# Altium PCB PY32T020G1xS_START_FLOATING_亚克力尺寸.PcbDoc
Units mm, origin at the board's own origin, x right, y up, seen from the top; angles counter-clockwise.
Board outline 150 x 47.08 mm, 2 copper layers (Top Layer, Bottom Layer); 6 components, 46 nets, 6 pads, 0 vias.
Unrouted connection lines stored in the file: 5.
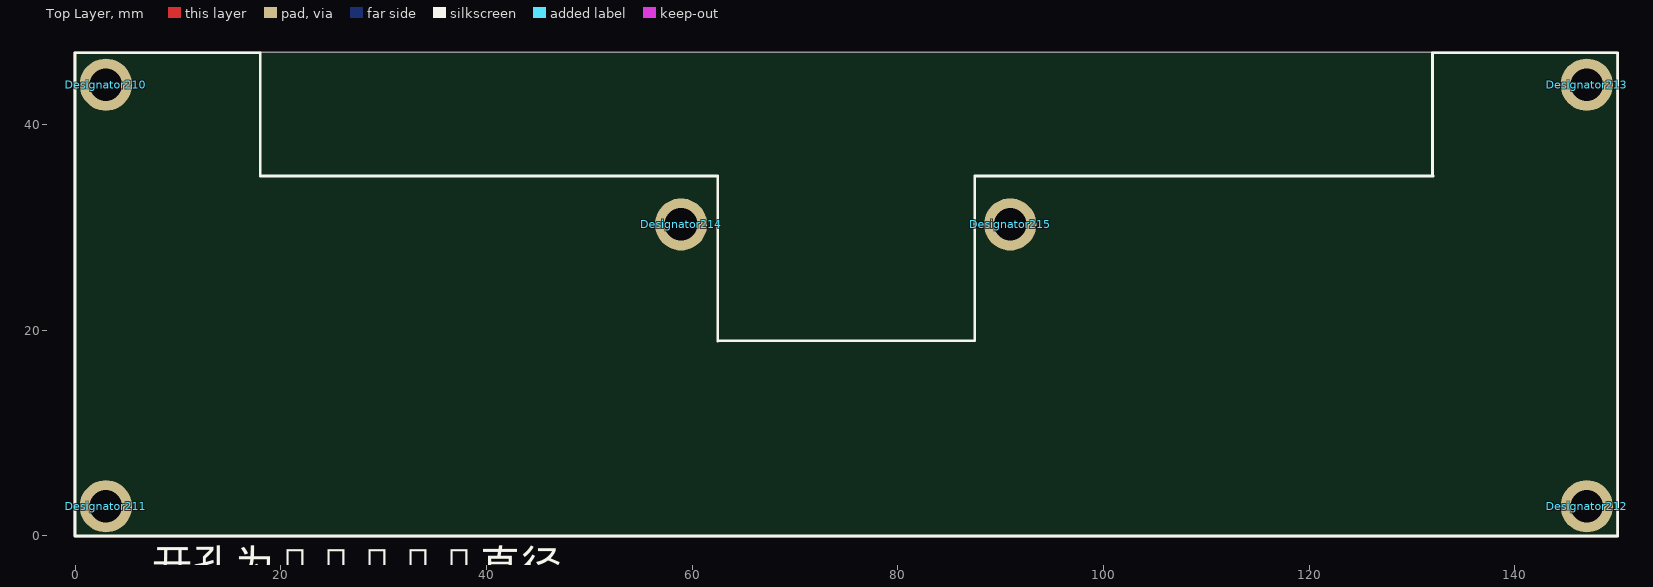
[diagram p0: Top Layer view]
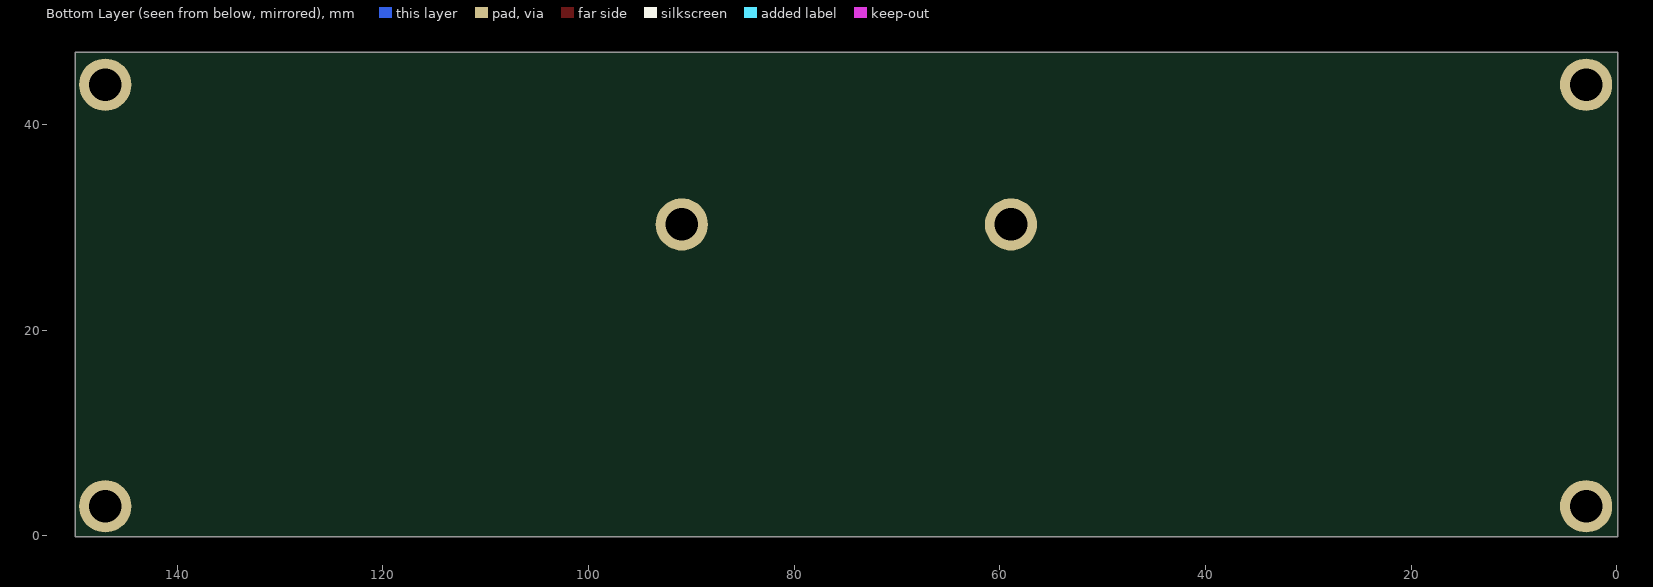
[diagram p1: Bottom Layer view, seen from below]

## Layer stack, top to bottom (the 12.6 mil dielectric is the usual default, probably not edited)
Top Solder: solder mask 0.0102, Solder Resist, Dk 3.5
Top Layer: signal copper 0.0356
Dielectric 1: dielectric 0.32, FR-4, Dk 4.8
Bottom Layer: signal copper 0.0356
Bottom Solder: solder mask 0.0102, Solder Resist, Dk 3.5

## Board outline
-0.064,-0.064 -0.064,47.015 149.936,47.015 149.936,-0.064

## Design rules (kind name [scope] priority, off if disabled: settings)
Clearance tk1 [InNet('NetR13_2')] p1: gap=0.7 ignorepadtopadclearanceinfootprint=FALSE
Clearance tk1_5 [InNet('NetR10_2')] p2: gap=0.7 ignorepadtopadclearanceinfootprint=FALSE
Clearance tk1_4 [InNet('NetR5_2')] p3: gap=0.7 ignorepadtopadclearanceinfootprint=FALSE
Clearance tk1_3 [InNet('NetR4_2')] p4: gap=0.7 ignorepadtopadclearanceinfootprint=FALSE
Clearance tk1_2 [InNet('NetR2_2')] p5: gap=0.7 ignorepadtopadclearanceinfootprint=FALSE
Clearance tk1_1 [InNet('NetR1_2')] p6: gap=0.7 ignorepadtopadclearanceinfootprint=FALSE
Clearance [All] p7: gap=0.254 ignorepadtopadclearanceinfootprint=FALSE
PlaneConnect [All] p1: planeconnectstyle=Direct reliefexpansion=0.508 reliefentries=4 reliefconductorwidth=0.254 reliefairgap=0.254
PolygonConnect [All] p1: connectstyle=Direct reliefconductorwidth=0.254 reliefentries=4 polygonreliefangle="90 Angle" airgapwidth=0.254
RoutingVias [All] p1: holewidth=0.711 width=1.27 viastyle="Through Hole" minholewidth=0.711 minwidth=1.27 maxholewidth=0.711 maxwidth=1.27
SolderMaskExpansion [All] p1: expansion=0.102 istentingtop=FALSE
Width [All] p1: maxlimit=0.6 minlimit=0.254 preferedwidth=0.254
29 further rules are at their usual default settings.

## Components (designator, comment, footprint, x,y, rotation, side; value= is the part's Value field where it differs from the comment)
Designator210 "Comment" "M3 125X200"#1 3.287,43.741 r0 top
Designator211 "Comment" "M3 125X200"#2 2.906,3.101 r0 top
Designator212 "Comment" "M3 125X200"#3 146.67,3.228 r0 top
Designator213 "Comment" "M3 125X200"#4 146.416,43.741 r0 top
Designator214 "Comment" "M3 125X200"#5 58.151,31.295 r0 top
Designator215 "Comment" "M3 125X200"#6 90.282,53.647 r0 top

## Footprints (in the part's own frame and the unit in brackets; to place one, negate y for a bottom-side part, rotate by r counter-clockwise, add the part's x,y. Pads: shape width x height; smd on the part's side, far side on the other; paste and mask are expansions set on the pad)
"M3 125X200"#1 [mm] "M3螺丝孔，孔125Mil，焊盘200Mil"
  round 5.08 hole 3.175: 1(-0.287,0.132)
"M3 125X200"#2 [mm] "M3螺丝孔，孔125Mil，焊盘200Mil"
  round 5.08 hole 3.175: 1(0.094,-0.228)
"M3 125X200"#3 [mm] "M3螺丝孔，孔125Mil，焊盘200Mil"
  round 5.08 hole 3.175: 1(0.33,-0.355)
"M3 125X200"#4 [mm] "M3螺丝孔，孔125Mil，焊盘200Mil"
  round 5.08 hole 3.175: 1(0.584,0.132)
"M3 125X200"#5 [mm] "M3螺丝孔，孔125Mil，焊盘200Mil"
  round 5.08 hole 3.175: 1(0.779,-1.008)
"M3 125X200"#6 [mm] "M3螺丝孔，孔125Mil，焊盘200Mil"
  round 5.08 hole 3.175: 1(0.648,-23.36)

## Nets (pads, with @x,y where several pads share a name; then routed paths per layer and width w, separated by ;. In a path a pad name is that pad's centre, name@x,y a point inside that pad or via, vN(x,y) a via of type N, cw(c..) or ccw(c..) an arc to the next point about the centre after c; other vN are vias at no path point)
BEEP: 
GND: Designator210.1 Designator211.1 Designator212.1 Designator213.1 Designator214.1 Designator215.1
LED1: 
LED2: 
LED3: 
LED4: 
LED5: 
LED6: 
Net1_1: 
Net1_2: 
NetBEEP1_2: 
NetLED1_1: 
NetLED2_2: 
NetLED3_2: 
NetLED4_2: 
NetLED5_2: 
NetLED6_2: 
NetLED8_2: 
NetQ1_1: 
NetQ1_3: 
NetR1_2: 
NetR2_2: 
NetR3_2: 
NetR4_2: 
NetR5_2: 
NetR8_2: 
NetR10_2: 
NetR13_2: 
NRST: 
SEGA: 
SEGB: 
SEGC: 
SEGD: 
SEGE: 
SEGF: 
SWCLK: 
SWDIO: 
TK1: 
TK2: 
TK3: 
TK4: 
TK5: 
TK6: 
V5V: 
VBUS: 
VCC: 

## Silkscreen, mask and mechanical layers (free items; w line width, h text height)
Top Overlay:
  lines w0.254: 0,-0.01 150,-0.01 150,46.99 132.08,46.99 ; 0,0 0,46.99 18,46.99 18,34.99 62.5,34.99 62.5,18.923 ; 62.5,18.99 87.5,18.99 87.5,34.99 132.08,34.99 ; 132,34.99 132,46.99
  text "开孔为3.175直径" at 7.437,-5.134 h5

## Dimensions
90.93,30.287 to 87.5,34.99 on Mechanical 1
90.93,30.287 to 87.5,34.99 on Mechanical 1
58.93,30.287 to 62.5,34.99 on Mechanical 1
58.93,30.287 to 62.5,34.99 on Mechanical 1
132,46.99 to 150,46.99 on Mechanical 1
147,43.873 to 150,46.99 on Mechanical 1
147,43.873 to 150,46.99 on Mechanical 1
147,2.873 to 150,-0.01 on Mechanical 1
147,2.873 to 150,-0.01 on Mechanical 1
3,43.873 to 0,46.99 on Mechanical 1
3,43.873 to 0,46.99 on Mechanical 1
3,2.873 to 0,-0.01 on Mechanical 1
3,2.873 to 0,-0.01 on Mechanical 1
0,46.99 to 18,46.99 on Mechanical 1
62.5,18.99 to 87.5,18.99 on Mechanical 1
132,34.99 to 87.5,34.99 on Mechanical 1
18,34.99 to 62.5,34.99 on Mechanical 1
62.5,34.99 to 62.5,18.99 on Mechanical 1
18,46.99 to 18,34.99 on Mechanical 1
0,-0.01 to 0,46.99 on Mechanical 1
0,-0.01 to 150,-0.01 on Mechanical 1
